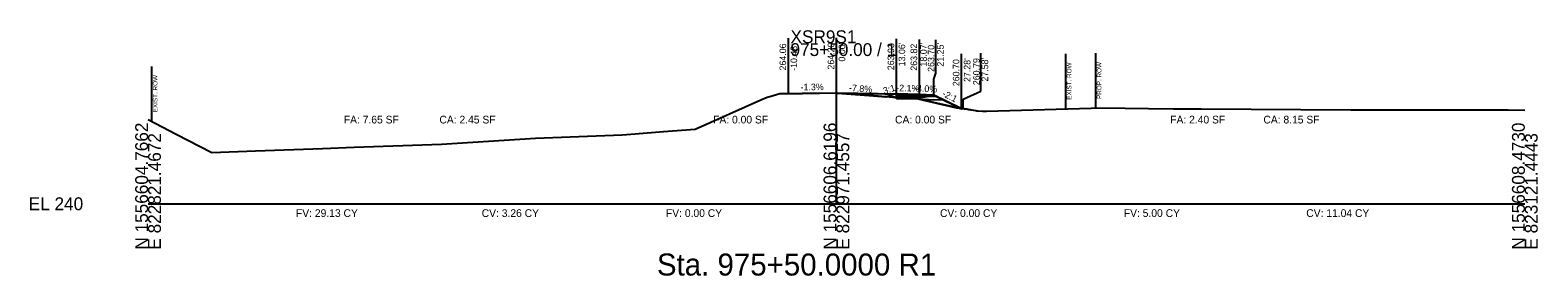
# Model space of a CAD drawing. Extents: x -26 to 823017, y -16 to 1558356.
# Drawn here: x 1974.3 to 2302.8, y 6984.3 to 7037.8 of the extents above; entities that cross this region are included whole.
import ezdxf

# ---------------------------------------------------------------- set-up
doc = ezdxf.new("R2010")
doc.units = 0
for name, color, linetype in [('ASPHALT_19MM1', 7, 'Continuous'), ('CONST_DCH', 7, 'Continuous'), ('CONST_LV3', 7, 'Continuous'), ('Draft_XS_Grid', 7, 'Continuous'), ('Draft_XS_Text', 7, 'Continuous'), ('DTM_CORRIDOR', 7, 'Continuous'), ('DTM_P_FINISHED_GRADE2', 7, 'Continuous'), ('DTM_X_GROUND', 7, 'Continuous'), ('SLOPE_STAKES_FILL', 7, 'Continuous'), ('X_TRANS_EOP', 7, 'Continuous'), ('XS_CELL', 7, 'Continuous'), ('XS_P_ASPHALT', 7, 'Continuous'), ('XS_P_DR_GRAVEL', 7, 'Continuous'), ('XS_P_GROUND', 7, 'Continuous'), ('XS_P_NULL_POINT', 7, 'Continuous'), ('XS_P_ROW', 7, 'Continuous'), ('XS_P_SHOULDER', 7, 'Continuous'), ('XS_P_SUBGRADE_GRANULAR', 7, 'Continuous'), ('XS_P_SUBGRADE_LEVELING', 7, 'Continuous'), ('XS_P_SUBGRADE_MILLING', 7, 'Continuous'), ('XS_P_SUBGRADE_UNDERCUT', 7, 'Continuous'), ('XS_P_TX_CLEARZONE', 7, 'Continuous'), ('XS_P_TX_FS_BS', 7, 'Continuous'), ('XS_SHEET_EW_TX_AREA', 7, 'Continuous'), ('XS_SHEET_EW_TX_VOLUME', 7, 'Continuous'), ('XS_X_ROW', 7, 'Continuous')]:
    doc.layers.add(name, color=color, linetype=linetype)

msp = doc.modelspace()

# ---------------------------------------------------------------- linework, layer by layer
at = {"layer": 'ASPHALT_19MM1'}
msp.add_lwpolyline([(2163.06, 7023.76), (2163.06, 7023.55), (2168.07, 7023.45), (2168.07, 7023.66), (2163.06, 7023.76)], dxfattribs=at)
at = {"layer": 'CONST_LV3'}
for points in [[(2000, 7018.39), (2006.12, 7015.15), (2013.86, 7011.16), (2023.4, 7011.51), (2037.99, 7012.06), (2044.88, 7012.32), (2063.93, 7013.02), (2084.39, 7014.28), (2103.29, 7015.02), (2106.16, 7015.25), (2112.35, 7015.74), (2119.23, 7016.29), (2133.49, 7022.62), (2134.94, 7023.26), (2135.47, 7023.41), (2137.67, 7024.04), (2139.52, 7024.06), (2139.52, 7024.06)], [(2150, 7024.2), (2164, 7023.92)], [(2160.77, 7023.36), (2160.77, 7023.36), (2163.06, 7023.18), (2163.4, 7023.17), (2168.07, 7023.07), (2170.86, 7023.62), (2171.25, 7023.7), (2176.23, 7021.22), (2177.75, 7020.73), (2177.78, 7020.74), (2177.85, 7020.76), (2178.44, 7020.66), (2178.68, 7020.61), (2180.37, 7020.31), (2180.4, 7020.31), (2180.58, 7020.28), (2180.87, 7020.24), (2181.8, 7020.18), (2182.68, 7020.17), (2208.07, 7020.89), (2212.95, 7020.82), (2218, 7020.75), (2223.43, 7020.68), (2229.44, 7020.67), (2262.11, 7020.44), (2267.48, 7020.44), (2273.34, 7020.44), (2279.75, 7020.45), (2286.81, 7020.45), (2294.61, 7020.45), (2296.39, 7020.44), (2300, 7020.42)], [(2162.77, 7023.97), (2162.77, 7023.97), (2164, 7023.92)]]:
    msp.add_lwpolyline(points, dxfattribs=at)
at = {"layer": 'DTM_P_FINISHED_GRADE2'}
msp.add_lwpolyline([(2139.52, 7024.06), (2150, 7024.2), (2160.77, 7023.98)], dxfattribs=at)
at = {"layer": 'DTM_X_GROUND'}
for points in [[(2000, 7018.39), (2006.12, 7015.15), (2013.86, 7011.16), (2023.4, 7011.51), (2037.99, 7012.06), (2044.88, 7012.32), (2063.93, 7013.02), (2084.39, 7014.28), (2103.29, 7015.02), (2106.16, 7015.25), (2112.35, 7015.74), (2119.23, 7016.29), (2133.49, 7022.62), (2134.94, 7023.26), (2135.47, 7023.41), (2137.67, 7024.04), (2142.64, 7024.11), (2150.21, 7024.2), (2159.07, 7024.02), (2163.06, 7023.93), (2164.47, 7023.64), (2164.63, 7023.61), (2176.18, 7020.94), (2178.44, 7020.6), (2178.68, 7020.56), (2180.87, 7020.24), (2181.8, 7020.18), (2182.68, 7020.17), (2208.07, 7020.89), (2212.95, 7020.82), (2218, 7020.75), (2223.43, 7020.68), (2229.44, 7020.67), (2262.11, 7020.44), (2267.48, 7020.44), (2273.34, 7020.44), (2279.75, 7020.45), (2286.81, 7020.45), (2294.61, 7020.45), (2296.39, 7020.44), (2300, 7020.42)], [(2000, 7018.39), (2006.12, 7015.15), (2013.86, 7011.16), (2023.4, 7011.51), (2037.99, 7012.06), (2044.88, 7012.32), (2063.93, 7013.02), (2084.39, 7014.28), (2103.29, 7015.02), (2106.16, 7015.25), (2112.35, 7015.74), (2119.23, 7016.29), (2133.49, 7022.62), (2134.94, 7023.26), (2135.47, 7023.41), (2137.67, 7024.04), (2142.64, 7024.11), (2150.21, 7024.2), (2159.07, 7023.5), (2163.06, 7023.18), (2163.4, 7023.17), (2168.07, 7023.07), (2170.86, 7023.62), (2171.25, 7023.7), (2176.23, 7021.22), (2177.75, 7020.73), (2177.78, 7020.74), (2177.85, 7020.76), (2178.44, 7020.66), (2178.68, 7020.61), (2180.37, 7020.31), (2180.4, 7020.31), (2180.58, 7020.28), (2180.87, 7020.24), (2181.8, 7020.18), (2182.68, 7020.17), (2208.07, 7020.89), (2212.95, 7020.82), (2218, 7020.75), (2223.43, 7020.68), (2229.44, 7020.67), (2262.11, 7020.44), (2267.48, 7020.44), (2273.34, 7020.44), (2279.75, 7020.45), (2286.81, 7020.45), (2294.61, 7020.45), (2296.39, 7020.44), (2300, 7020.42)], [(2000, 7018.39), (2006.12, 7015.15), (2013.86, 7011.16), (2023.4, 7011.51), (2037.99, 7012.06), (2044.88, 7012.32), (2063.93, 7013.02), (2084.39, 7014.28), (2103.29, 7015.02), (2106.16, 7015.25), (2112.35, 7015.74), (2119.23, 7016.29), (2133.49, 7022.62), (2134.94, 7023.26), (2135.47, 7023.41), (2137.67, 7024.04), (2139.52, 7024.06), (2139.52, 7024.06), (2150, 7024.2), (2150, 7024.2), (2150, 7024.2), (2150, 7024.2), (2150, 7024.2), (2150, 7024.2), (2150, 7024.2), (2160.77, 7023.98), (2160.77, 7023.98), (2160.77, 7023.98), (2163.06, 7023.18), (2163.4, 7023.17), (2168.07, 7023.07), (2170.86, 7023.62), (2171.25, 7023.7), (2176.23, 7021.22), (2177.75, 7020.73), (2177.78, 7020.74), (2177.85, 7020.76), (2178.44, 7020.66), (2178.68, 7020.61), (2180.37, 7020.31), (2180.4, 7020.31), (2180.58, 7020.28), (2180.87, 7020.24), (2181.8, 7020.18), (2182.68, 7020.17), (2208.07, 7020.89), (2212.95, 7020.82), (2218, 7020.75), (2223.43, 7020.68), (2229.44, 7020.67), (2262.11, 7020.44), (2267.48, 7020.44), (2273.34, 7020.44), (2279.75, 7020.45), (2286.81, 7020.45), (2294.61, 7020.45), (2296.39, 7020.44), (2300, 7020.42)]]:
    msp.add_lwpolyline(points, dxfattribs=at)
at = {"layer": 'X_TRANS_EOP'}
msp.add_lwpolyline([(2163.06, 7023.93), (2163.06, 7023.76), (2168.07, 7023.66), (2168.07, 7023.82), (2163.06, 7023.93)], dxfattribs=at)
at = {"layer": 'XS_CELL'}
for p, q in [((2150, 7000), (2150, 7035)), ((2000, 7000), (2150, 7000)), ((2150, 7000), (2300, 7000))]:
    msp.add_line(p, q, dxfattribs=at)
at = {"layer": 'XS_P_ASPHALT'}
msp.add_lwpolyline([(2139.52, 7024.06), (2150, 7024.2), (2150, 7024.2), (2160.77, 7023.36), (2160.77, 7023.36), (2160.77, 7023.24), (2160.77, 7023.24), (2150, 7024.08), (2150, 7024.08), (2139.52, 7023.94), (2139.52, 7024.06)], dxfattribs=at)
at = {"layer": 'XS_P_DR_GRAVEL'}
msp.add_lwpolyline([(2168.07, 7023.82), (2168.07, 7023.45), (2171.91, 7023.37), (2171.25, 7023.7), (2168.07, 7023.82)], dxfattribs=at)
at = {"layer": 'XS_P_GROUND'}
for points in [[(2162.88, 7023.93), (2162.88, 7023.93), (2162.77, 7023.97)], [(2177.58, 7020.73), (2176.18, 7020.94), (2176.18, 7020.94), (2164.63, 7023.61), (2164.63, 7023.61), (2164.47, 7023.64), (2164.47, 7023.64), (2163.06, 7023.93), (2163.06, 7023.93), (2162.88, 7023.93), (2162.88, 7023.93)], [(2162.88, 7023.93), (2162.88, 7023.93), (2163.06, 7023.93), (2163.06, 7023.93), (2164.47, 7023.64), (2164.47, 7023.64), (2164.63, 7023.61), (2164.63, 7023.61), (2176.18, 7020.94), (2176.18, 7020.94), (2177.58, 7020.73)], [(2171.25, 7023.7), (2177.28, 7020.7), (2177.58, 7020.79)]]:
    msp.add_lwpolyline(points, dxfattribs=at)
at = {"layer": 'XS_P_ROW'}
msp.add_line((2206.52, 7020.84), (2206.52, 7032.84), dxfattribs=at)
at = {"layer": 'XS_P_SHOULDER'}
msp.add_lwpolyline([(2168.07, 7023.82), (2171.25, 7023.7)], dxfattribs=at)
at = {"layer": 'XS_P_SUBGRADE_GRANULAR'}
for points in [[(2163.06, 7022.89), (2163.06, 7023.93)], [(2168.07, 7022.78), (2163.4, 7022.88), (2163.06, 7022.89)], [(2168.07, 7022.78), (2170.08, 7022.74), (2173.31, 7022.67)]]:
    msp.add_lwpolyline(points, dxfattribs=at)
at = {"layer": 'XS_P_SUBGRADE_LEVELING'}
msp.add_lwpolyline([(2160.77, 7023.24), (2159.07, 7023.37), (2159.07, 7023.37), (2150.21, 7024.06), (2150.21, 7024.06), (2150, 7024.08), (2142.64, 7023.98), (2142.64, 7023.98), (2139.52, 7023.94)], dxfattribs=at)
msp.add_lwpolyline([(2160.77, 7023.24), (2159.07, 7023.37), (2159.07, 7023.37), (2150.21, 7024.06), (2150.21, 7024.06), (2150, 7024.08), (2142.64, 7023.98), (2142.64, 7023.98), (2139.52, 7023.94)], dxfattribs=at)
at = {"layer": 'XS_P_SUBGRADE_MILLING'}
msp.add_lwpolyline([(2160.77, 7023.36), (2160.77, 7023.24), (2159.07, 7023.37), (2159.07, 7023.37), (2150.21, 7024.06), (2150.21, 7024.06), (2150, 7024.08), (2142.64, 7023.98), (2142.64, 7023.98), (2139.52, 7023.94), (2139.52, 7024.06), (2142.64, 7024.11), (2142.64, 7024.11), (2150, 7024.2), (2150.21, 7024.2), (2150.21, 7024.2), (2159.07, 7023.5), (2159.07, 7023.5), (2160.77, 7023.36)], dxfattribs=at)
at = {"layer": 'XS_P_SUBGRADE_UNDERCUT'}
msp.add_lwpolyline([(2163.06, 7023.93), (2164.63, 7023.61), (2177.03, 7020.81), (2171.25, 7023.7)], close=True, dxfattribs=at)
at = {"layer": 'XS_P_TX_CLEARZONE'}
for p, q in [((2139.52, 7024.06), (2139.52, 7036.06)), ((2150, 7024.2), (2150, 7036.2)), ((2163.06, 7023.93), (2163.06, 7035.93)), ((2168.07, 7023.82), (2168.07, 7035.82)), ((2171.63, 7028.48), (2171.63, 7035.7)), ((2177.28, 7020.7), (2177.28, 7032.7)), ((2181.44, 7024.56), (2181.44, 7032.79)), ((2171.25, 7027.14), (2171.63, 7028.48)), ((2171.25, 7023.7), (2171.25, 7027.14)), ((2171.25, 7027.14), (2171.25, 7027.14)), ((2177.58, 7022.76), (2181.44, 7024.56)), ((2177.58, 7020.79), (2177.58, 7022.76))]:
    msp.add_line(p, q, dxfattribs=at)
at = {"layer": 'XS_X_ROW'}
for p, q in [((2200, 7020.66), (2200, 7032.66)), ((2000.84, 7017.94), (2000.84, 7029.94))]:
    msp.add_line(p, q, dxfattribs=at)

# ---------------------------------------------------------------- texts
at = {"layer": 'CONST_DCH'}
for p in [(2139.44, 7023.94), (2149.92, 7024.08), (2160.69, 7023.24)]:
    msp.add_text('X', height=0.24, dxfattribs=at).set_placement(p)
at = {"layer": 'CONST_LV3'}
for p in [(2162.69, 7023.85), (2162.8, 7023.81), (2177.5, 7020.67)]:
    msp.add_text('X', height=0.24, dxfattribs=at).set_placement(p)
at = {"layer": 'Draft_XS_Grid'}
msp.add_text('-', height=0.0001, dxfattribs=at).set_placement((2000, 7000))
at = {"layer": 'Draft_XS_Text'}
msp.add_text('Sta. 975+50.0000 R1', height=4.8, dxfattribs=at).set_placement((2110.88, 6984.35))
at = {"layer": 'DTM_CORRIDOR'}
for p in [(2162.98, 7023.81), (2167.99, 7023.7)]:
    msp.add_text('X', height=0.24, dxfattribs=at).set_placement(p)
at = {"layer": 'SLOPE_STAKES_FILL'}
msp.add_text('X', height=0.24, dxfattribs=at).set_placement((2177.2, 7020.58))
at = {"layer": 'XS_CELL'}
for s, p in [('XSR9S1', (2140, 7035)), ('975+50.00 / 1', (2140, 7032.2)), ('EL 240', (1974, 6998.6))]:
    msp.add_text(s, height=2.8, dxfattribs=at).set_placement(p)
for s, p in [('N 1556604.7662', (2000, 6990)), ('N 1556606.6196', (2150, 6990)), ('N 1556608.4730', (2300, 6990)), ('E 822821.4672', (2002.8, 6990)), ('E 822971.4557', (2152.8, 6990)), ('E 823121.4443', (2302.8, 6990))]:
    msp.add_text(s, height=2.8, rotation=90, dxfattribs=at).set_placement(p)
at = {"layer": 'XS_P_NULL_POINT'}
msp.add_text('X', height=0.24, dxfattribs=at).set_placement((2177.5, 7020.67))
at = {"layer": 'XS_P_ROW'}
msp.add_text('PROP. ROW', height=1, rotation=90, dxfattribs=at).set_placement((2207.73, 7022.84))
at = {"layer": 'XS_P_SHOULDER'}
msp.add_text('X', height=0.24, dxfattribs=at).set_placement((2171.17, 7023.58))
at = {"layer": 'XS_P_TX_CLEARZONE'}
for s, p in [('264.06', (2139.04, 7029.05)), ("-10.48'", (2141.44, 7028.97)), ('264.20', (2149.52, 7029.25)), ("0.00'", (2151.92, 7030.99)), ('263.93', (2162.58, 7029.11)), ("13.06'", (2164.98, 7029.95)), ('263.82', (2167.59, 7029)), ("18.07'", (2169.69, 7029.91)), ('263.70', (2171.35, 7028.75)), ("21.25'", (2173.37, 7029.89)), ('260.70', (2176.8, 7025.63)), ("27.28'", (2179.2, 7026.53)), ('260.79', (2181.22, 7025.85)), ("27.58'", (2183.07, 7026.63))]:
    msp.add_text(s, height=1.44, rotation=90, dxfattribs=at).set_placement(p)
at = {"layer": 'XS_P_TX_FS_BS'}
for s, rotation, p in [('-1.3%', 0.7548, (2142.2, 7024.7)), ('-7.8%', 355.5387, (2152.7, 7024.59)), ('3:1', 16.9487, (2160.42, 7023.88)), ('-2.1%', 358.8011, (2163.02, 7024.53)), ('-4.0%', 357.7075, (2166.89, 7024.47)), ('-2:1', 333.525, (2172.91, 7023.54))]:
    msp.add_text(s, height=1.44, rotation=rotation, dxfattribs=at).set_placement(p)
at = {"layer": 'XS_SHEET_EW_TX_AREA'}
for s, p in [('FA: 7.65 SF', (2042.65, 7017.5)), ('CA: 2.45 SF', (2063.49, 7017.5)), ('FA: 0.00 SF', (2123.13, 7017.5)), ('CA: 0.00 SF', (2162.77, 7017.5)), ('FA: 2.40 SF', (2222.73, 7017.5)), ('CA: 8.15 SF', (2243.04, 7017.5))]:
    msp.add_text(s, height=1.68, dxfattribs=at).set_placement(p)
at = {"layer": 'XS_SHEET_EW_TX_VOLUME'}
for s, p in [('FV: 29.13 CY', (2032.23, 6997.12)), ('CV: 3.26 CY', (2072.7, 6997.12)), ('FV: 0.00 CY', (2112.85, 6997.12)), ('CV: 0.00 CY', (2172.56, 6997.12)), ('FV: 5.00 CY', (2212.62, 6997.12)), ('CV: 11.04 CY', (2252.38, 6997.12))]:
    msp.add_text(s, height=1.68, dxfattribs=at).set_placement(p)
at = {"layer": 'XS_X_ROW'}
for p in [(2002.04, 7019.94), (2201.2, 7022.66)]:
    msp.add_text('EXIST. ROW', height=1, rotation=90, dxfattribs=at).set_placement(p)

doc.saveas('drawing.dxf')
